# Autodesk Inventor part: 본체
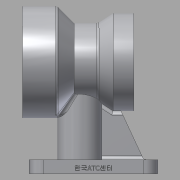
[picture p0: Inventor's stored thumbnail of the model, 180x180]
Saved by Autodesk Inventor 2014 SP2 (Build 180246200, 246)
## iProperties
Created: 2019-01
Part Number: 본체
Material: 알루미늄 6061
Document SubType Name: Modeling
Designer: CM-CAD
Density: 2.71 g/cm^3
Appearance: 알루미늄 - 평지
Mass: 886.283 g
Surface Area: 616.56 cm^2
Volume: 327.042 cm^3
Author: CM-CAD
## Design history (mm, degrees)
sketch "스케치1"
  geometry: C1 r 40 at (0, 0); 1 further point
  constraints: 1 centre point, 1 coincident
  dimensions: "d0" = 80 diameter of C1
extrude "돌출1" new body sketch "스케치1" distance "d1" = 80; taper "d2" = 0 deg
sketch "스케치2"
  geometry: L1 (0, 40)-(0, -40) reference; L2 (80, -40)-(80, 40) reference; L3 (0, 0)-(80, 0); L4 (0, 40)-(25, 40); L5 (25, 40)-(37.155, 28); L6 (37.155, 28)-(54.213, 28); L7 (54.213, 28)-(65, 35); L8 (65, 35)-(80, 35)
  constraints: 12 end point, 2 parallel, 2 point on line, 1 midpoint, 1 perpendicular
  dimensions: "d3" = 25 distance of L4.start L4.end; "d4" = 15 distance of L7.end L8.end; "d5" = 80 diameter of L4 L3; "d6" = 56 diameter of L6 L3; "d7" = 70 diameter of L8 L3
revolve "회전1" sketch "스케치2" stored, may be unused: angle "d8" = 90 deg
sketch "스케치3"
  geometry: L1 (0, 40)-(0, -40) reference; L2 (80, 35)-(80, -35) reference; L3 (0, 0)-(80, 0); L4 (0, 26)-(20, 26); L5 (20, 26)-(20, 16); L6 (20, 16)-(63, 16); L7 (63, 16)-(63, 20); L8 (63, 20)-(80, 20)
  constraints: 12 end point, 3 perpendicular, 2 parallel, 2 point on line, 1 midpoint
  dimensions: "d9" = 52 diameter of L4 L3; "d10" = 32 diameter of L6 L3; "d11" = 40 diameter of L8 L3; "d12" = 20 distance of L4.start L4.end; "d13" = 17 distance of L7.end L8.end
revolve "회전2" sketch "스케치3" stored, may be unused: angle "d14" = 90 deg
fillet "모깎기1" dims "d15" = 1
chamfer "모따기1" distance "d16" = 1; stored, may be unused: second distance "d17" = 2, angle "d18" = 45 deg
sketch "스케치4" dims "d19" = 66
  geometry: C1 r 27 at (0, 0) reference; 2 further points
  constraints: 1 coincident, 1 vertical alignment, 2 other
hole "구멍1" sketch "스케치4" at (0, 33) diameter "d20" = 3.242; stored, may be unused: countersink angle "d24" = 90 deg, drill point angle "d26" = 118 deg; dims "d21" = 9, "d22" = 4, "d23" = 2, "d25" = 11
sketch "스케치5" dims "d30" = 55
  geometry: C1 r 21 at (0, 0) reference; 2 further points
  constraints: 1 coincident, 1 vertical alignment, 2 other
hole "구멍2" sketch "스케치5" at (0, 27.5) diameter "d31" = 3.242; stored, may be unused: countersink angle "d35" = 90 deg, drill point angle "d37" = 118 deg; dims "d32" = 9, "d33" = 4, "d34" = 2, "d36" = 11
node "작업 평면1"
sketch "스케치6"
  geometry: L1 (40, 25)-(-40, 25) reference; L2 (-40, 57)-(40, 57); L3 (-40, 25)-(40, 25); L4 (-44.948, 41)-(42.771, 41); C1 r 16 at (0, 41); 2 further points
  constraints: 6 end point, 2 parallel, 1 centre point, 1 collinear, 1 midpoint, 1 point on line
  dimensions: "d42" = 32 distance between parallel lines of L2 L1; "d43" = 16 distance between parallel lines of L2 L4; "d44" = 32 diameter of C1
extrude "돌출2" join sketch "스케치6" distance "d45" = 20; taper "d46" = 0 deg
sketch "스케치7"
  geometry: 3 further points
  constraints: 1 vertical alignment
extrude "돌출3" join sketch "스케치7" distance "d47" = 40; taper "d48" = 0 deg
sketch "스케치8"
  geometry: L1 (0, 0)-(-46, 0); L2 (-46, -36)-(48.584, -36); L3 (-46, -36)-(-46, 56); L4 (46, -36)-(46, 56); L5 (-46, 56)-(46, 56); C1 r 16 at (0, 0) reference; 1 further point
  constraints: 10 end point, 2 parallel, 2 perpendicular, 2 point on line, 1 horizontal
  dimensions: "d49" = 36 distance between parallel lines of L2 L1; "d50" = 46 distance from line of L3 L1.start; "d51" = 92 distance between parallel lines of L4 L3; "d52" = 92 distance between parallel lines of L5 L2
extrude "돌출4" join sketch "스케치8" distance "d53" = 10; taper "d54" = 0 deg
sketch "스케치9"
  geometry: L1 (97, 70)-(5, 70) reference; L2 (80, 35)-(65, 35) reference; L3 (65, 35)-(57, 29.809) reference; L4 (57, 70)-(57, 29.809) reference; L5 (57, 5.665)-(87, 70); L6 (97, 80)-(97, 70) reference; 2 further points
  constraints: 4 point on line, 2 end point
  dimensions: "d55" = 25 deg angle of L6 L5; "d56" = 10 distance of L1.start L5.end
extrude "돌출5" join sketch "스케치9" stored distance "d57" = 10; taper "d58" = 0 deg
fillet "모깎기2" dims "d59" = 10
sketch "스케치10"
  geometry: A1 r 10 centre (-36, -26) between (-46, -26) and (-36, -36) reference; A2 r 10 centre (36, -26) between (36, -36) and (46, -26) reference; A3 r 10 centre (36, 46) between (46, 46) and (36, 56) reference; A4 r 10 centre (-36, 46) between (-36, 56) and (-46, 46) reference; 5 further points
  constraints: 4 coincident
hole "구멍3" sketch "스케치10" at (-36, 46), (36, 46), (36, -26), (-36, -26) diameter "d60" = 9; stored, may be unused: countersink angle "d64" = 90 deg, drill point angle "d66" = 118 deg; dims "d61" = 9, "d62" = 4, "d63" = 2, "d65" = 10
fillet "모깎기3" dims "d67" = 3
fillet "모깎기4" dims "d68" = 3
fillet "모깎기5" dims "d69" = 3
fillet "모깎기6" dims "d70" = 3
fillet "모깎기7" dims "d71" = 3
fillet "모깎기8" dims "d72" = 3
fillet "모깎기9" dims "d73" = 3
fillet "모깎기10" dims "d74" = 3
fillet "모깎기11" dims "d75" = 3
fillet "모깎기12" dims "d76" = 3
fillet "모깎기13" dims "d77" = 3
fillet "모깎기14" dims "d78" = 3
fillet "모깎기15" dims "d79" = 3
fillet "모깎기16" dims "d80" = 3
fillet "모깎기17" dims "d81" = 3
fillet "모깎기18" dims "d82" = 3
sketch "스케치11"
  geometry: L1 (0, 0)-(0, 72) reference; L2 (-10, -10)-(0, -10) reference; 2 further points
  constraints: 1 other
  dimensions: "d83" = 46 distance from line of point (-4, 36) L2; "d84" = 4 distance from line of L1 point (-4, 36)
feature "엠보싱1" sketch "스케치11" dims "d0" = 80, "d9" = 52, "d10" = 32, "d11" = 40, "d12" = 20, "d13" = 17, "d85" = 0.5, "d86" = 0
node "솔리드1"
pattern_circular "원형 패턴1" dims angle "d28" = 360 deg
pattern_circular "원형 패턴2" dims angle "d39" = 360 deg
